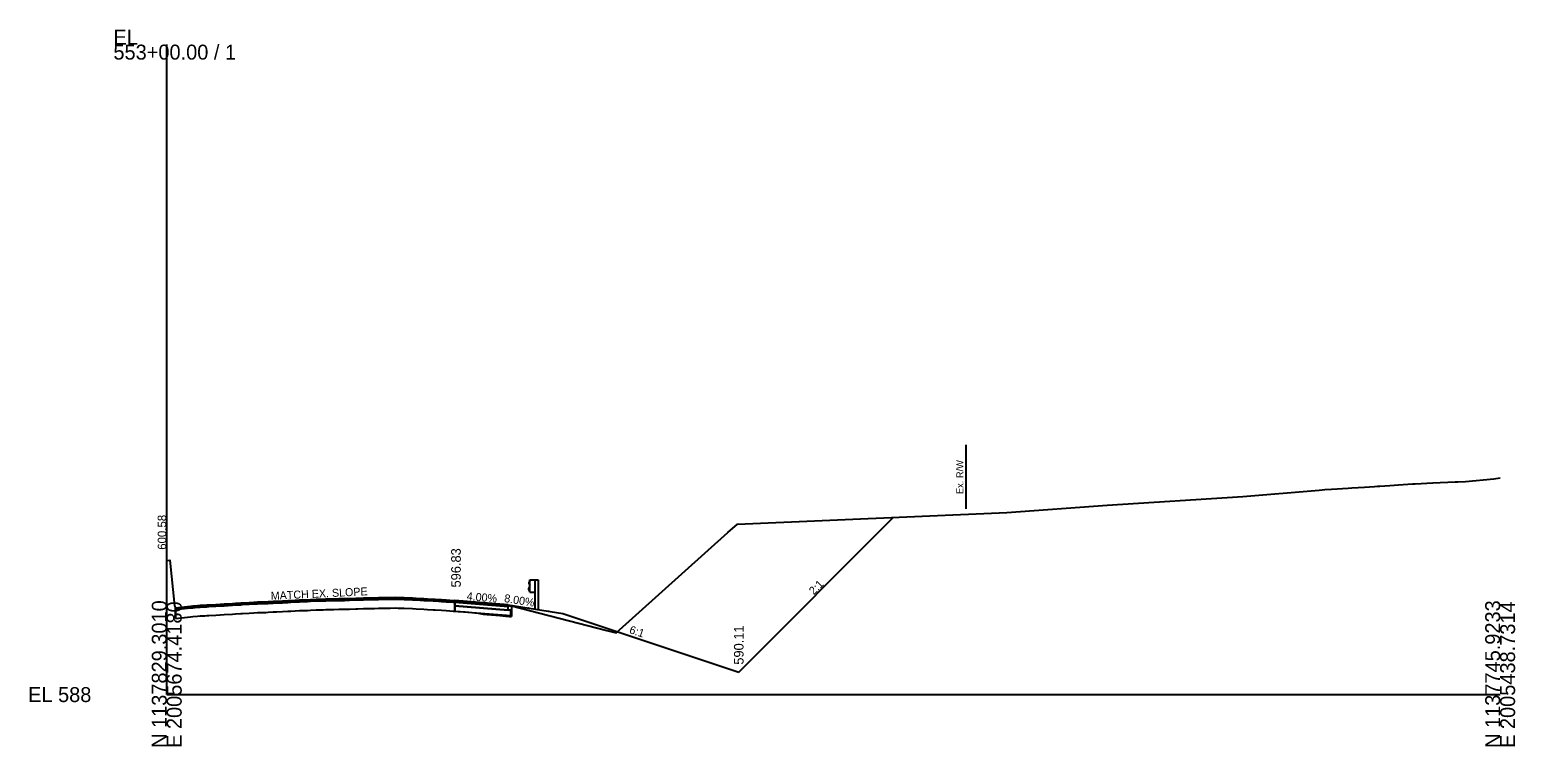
# Model space of a CAD drawing. Extents: x -201 to 2007062, y -213 to 1139737.
# Drawn here: x -25.7 to 252.8, y 7490.3 to 7624.7 of the extents above; entities that cross this region are included whole.
import ezdxf

# ---------------------------------------------------------------- set-up
doc = ezdxf.new("R2010")
doc.units = 0
for name, color, linetype in [('Default', 7, 'Continuous'), ('RD_GPK_XS_Cell', 7, 'Continuous'), ('RD_Sketch1', 7, 'Continuous'), ('RD_XS_Base', 7, 'Continuous'), ('RD_XS_EarthShd', 7, 'Continuous'), ('RD_XS_ExGround', 7, 'Continuous'), ('RD_XS_ExPaveRet', 7, 'Continuous'), ('RD_XS_ExRW', 7, 'Continuous'), ('RD_XS_GR', 7, 'Continuous'), ('RD_XS_PaveOvlay', 7, 'Continuous'), ('RD_XS_PaveShd', 7, 'Continuous'), ('RD_XS_TieSlope', 7, 'Continuous'), ('RD_XS_TX_Ditch', 7, 'Continuous'), ('RD_XS_TX_Elev_EX', 7, 'Continuous'), ('RD_XS_TX_Elev_PR', 7, 'Continuous'), ('RD_XS_TX_Slope', 7, 'Continuous')]:
    doc.layers.add(name, color=color, linetype=linetype)

msp = doc.modelspace()

# ---------------------------------------------------------------- linework, layer by layer
at = {"layer": 'RD_GPK_XS_Cell'}
for q in [(0, 7621.9), (250, 7500)]:
    msp.add_line((0, 7500), q, dxfattribs=at)
at = {"layer": 'RD_XS_Base'}
for points in [[(64, 7516.52), (54, 7517.32)], [(54, 7517.32), (54, 7516.66)], [(64.5, 7515.82), (64, 7515.86), (54, 7516.66)], [(54, 7516.66), (54, 7515.66)], [(54, 7516.66), (64, 7515.86)], [(54, 7515.66), (64.5, 7514.82)], [(64, 7515.86), (64, 7516.52)], [(64.5, 7514.82), (64.5, 7515.82)]]:
    msp.add_lwpolyline(points, dxfattribs=at)
at = {"layer": 'RD_XS_EarthShd'}
msp.add_lwpolyline([(64, 7516.85), (74.25, 7515.21)], dxfattribs=at)
at = {"layer": 'RD_XS_ExGround'}
msp.add_lwpolyline([(0, 7525.17), (0.58, 7525.19), (1.48, 7516.66), (1.64, 7516.27), (4.45, 7516.58), (4.92, 7516.63), (5.75, 7516.72), (6.29, 7516.75), (7.12, 7516.8), (7.52, 7516.82), (7.87, 7516.83), (9.18, 7516.91), (9.99, 7516.97), (10.75, 7517.02), (12.32, 7517.11), (12.9, 7517.14), (13.88, 7517.2), (14.23, 7517.22), (15.45, 7517.29), (16.35, 7517.34), (17.02, 7517.38), (18.55, 7517.43), (19.01, 7517.45), (19.97, 7517.52), (20.6, 7517.54), (21.72, 7517.57), (22.72, 7517.63), (23.29, 7517.66), (24.89, 7517.76), (26.42, 7517.8), (26.96, 7517.84), (27.99, 7517.89), (29.35, 7517.92), (29.83, 7517.94), (30.75, 7517.97), (31.34, 7517.97), (32.27, 7518), (32.69, 7518), (33.33, 7518.02), (34.26, 7518.04), (35.45, 7518.09), (35.82, 7518.1), (36.88, 7518.13), (37.57, 7518.15), (38.96, 7518.17), (39.69, 7518.2), (40.52, 7518.22), (41.89, 7518.24), (42.9, 7518.25), (43.4, 7518.24), (43.93, 7518.22), (44.51, 7518.2), (46.05, 7518.13), (46.79, 7518.09), (48.18, 7518.01), (48.88, 7517.97), (49.93, 7517.92), (50.3, 7517.9), (51.49, 7517.81), (52.42, 7517.75), (53.06, 7517.71), (53.69, 7517.67), (54.64, 7517.61), (55.03, 7517.6), (55.92, 7517.51), (56.66, 7517.44), (57.76, 7517.34), (58.37, 7517.3), (59, 7517.15), (59.31, 7517.11), (60, 7517.01), (60.91, 7516.94), (62.46, 7516.83), (63.03, 7516.77), (63.6, 7516.7), (64.25, 7516.64), (64.66, 7516.63), (82.53, 7512.02), (84.29, 7511.58), (105.23, 7530.38), (107, 7531.96), (157.52, 7534.18), (176.33, 7535.52), (201.74, 7537.17), (216.08, 7538.37), (216.61, 7538.4), (217.12, 7538.44), (218.37, 7538.52), (221.52, 7538.73), (222.18, 7538.77), (224.59, 7538.93), (226.42, 7539.05), (227, 7539.08), (227.42, 7539.11), (229.32, 7539.24), (230.93, 7539.34), (233.56, 7539.51), (234.07, 7539.54), (237.38, 7539.7), (241.58, 7539.9), (242.05, 7539.92), (243.52, 7540), (248.82, 7540.5), (250, 7540.63)], dxfattribs=at)
at = {"layer": 'RD_XS_ExPaveRet'}
for p, q in [((1.64, 7514.27), (1.64, 7516.27)), ((1.64, 7515.94), (1.64, 7514.27)), ((7.12, 7514.8), (7.52, 7514.82)), ((7.12, 7514.8), (7.52, 7514.82)), ((7.52, 7514.82), (7.87, 7514.83)), ((7.52, 7514.82), (7.87, 7514.83)), ((7.87, 7514.83), (9.18, 7514.91)), ((7.87, 7514.83), (9.18, 7514.91)), ((9.18, 7514.91), (9.99, 7514.97)), ((9.18, 7514.91), (9.99, 7514.97)), ((9.99, 7514.97), (10.75, 7515.02)), ((9.99, 7514.97), (10.75, 7515.02)), ((10.75, 7515.02), (12.32, 7515.11)), ((10.75, 7515.02), (12.32, 7515.11)), ((12.32, 7515.11), (12.9, 7515.14)), ((12.32, 7515.11), (12.9, 7515.14)), ((12.9, 7515.14), (13.88, 7515.2)), ((12.9, 7515.14), (13.88, 7515.2)), ((13.88, 7515.2), (14.23, 7515.22)), ((13.88, 7515.2), (14.23, 7515.22)), ((14.23, 7515.22), (15.45, 7515.29)), ((14.23, 7515.22), (15.45, 7515.29)), ((15.45, 7515.29), (16.35, 7515.34)), ((15.45, 7515.29), (16.35, 7515.34)), ((16.35, 7515.34), (17.02, 7515.38)), ((16.35, 7515.34), (17.02, 7515.38)), ((17.02, 7515.38), (18.55, 7515.43)), ((17.02, 7515.38), (18.55, 7515.43)), ((18.55, 7515.43), (19.01, 7515.45)), ((18.55, 7515.43), (19.01, 7515.45)), ((19.01, 7515.45), (19.97, 7515.52)), ((19.01, 7515.45), (19.97, 7515.52)), ((19.97, 7515.52), (20.6, 7515.54)), ((19.97, 7515.52), (20.6, 7515.54)), ((20.6, 7515.54), (21.72, 7515.57)), ((20.6, 7515.54), (21.72, 7515.57)), ((21.72, 7515.57), (22.72, 7515.63)), ((21.72, 7515.57), (22.72, 7515.63)), ((22.72, 7515.63), (23.29, 7515.66)), ((22.72, 7515.63), (23.29, 7515.66)), ((23.29, 7515.66), (24.89, 7515.76)), ((23.29, 7515.66), (24.89, 7515.76)), ((24.89, 7515.76), (26.42, 7515.8)), ((24.89, 7515.76), (26.42, 7515.8)), ((26.42, 7515.8), (26.96, 7515.84)), ((26.42, 7515.8), (26.96, 7515.84)), ((26.96, 7515.84), (27.99, 7515.89)), ((26.96, 7515.84), (27.99, 7515.89)), ((27.99, 7515.89), (29.35, 7515.92)), ((27.99, 7515.89), (29.35, 7515.92)), ((29.35, 7515.92), (29.83, 7515.94)), ((29.35, 7515.92), (29.83, 7515.94)), ((29.83, 7515.94), (30.75, 7515.97)), ((29.83, 7515.94), (30.75, 7515.97)), ((30.75, 7515.97), (31.34, 7515.97)), ((30.75, 7515.97), (31.34, 7515.97)), ((31.34, 7515.97), (32.27, 7516)), ((31.34, 7515.97), (32.27, 7516)), ((32.27, 7516), (32.69, 7516)), ((32.27, 7516), (32.69, 7516)), ((32.69, 7516), (33.33, 7516.02)), ((32.69, 7516), (33.33, 7516.02)), ((33.33, 7516.02), (34.26, 7516.04)), ((33.33, 7516.02), (34.26, 7516.04)), ((34.26, 7516.04), (35.45, 7516.09)), ((34.26, 7516.04), (35.45, 7516.09)), ((35.45, 7516.09), (35.82, 7516.1)), ((35.45, 7516.09), (35.82, 7516.1)), ((35.82, 7516.1), (36.88, 7516.13)), ((35.82, 7516.1), (36.88, 7516.13)), ((36.88, 7516.13), (37.57, 7516.15)), ((36.88, 7516.13), (37.57, 7516.15)), ((37.57, 7516.15), (38.96, 7516.17)), ((37.57, 7516.15), (38.96, 7516.17)), ((38.96, 7516.17), (39.69, 7516.2)), ((38.96, 7516.17), (39.69, 7516.2)), ((39.69, 7516.2), (40.52, 7516.22)), ((39.69, 7516.2), (40.52, 7516.22)), ((40.52, 7516.22), (41.89, 7516.24)), ((40.52, 7516.22), (41.89, 7516.24)), ((41.89, 7516.24), (42.9, 7516.25)), ((41.89, 7516.24), (42.9, 7516.25)), ((42.9, 7516.25), (43.4, 7516.24)), ((42.9, 7516.25), (43.4, 7516.24)), ((43.4, 7516.24), (43.93, 7516.22)), ((43.4, 7516.24), (43.93, 7516.22)), ((43.93, 7516.22), (44.51, 7516.2)), ((43.93, 7516.22), (44.51, 7516.2)), ((44.51, 7516.2), (46.05, 7516.13)), ((44.51, 7516.2), (46.05, 7516.13)), ((46.05, 7516.13), (46.79, 7516.09)), ((46.05, 7516.13), (46.79, 7516.09)), ((46.79, 7516.09), (48.18, 7516.01)), ((46.79, 7516.09), (48.18, 7516.01)), ((48.18, 7516.01), (48.88, 7515.97)), ((48.18, 7516.01), (48.88, 7515.97)), ((48.88, 7515.97), (49.93, 7515.92)), ((48.88, 7515.97), (49.93, 7515.92)), ((49.93, 7515.92), (50.3, 7515.9)), ((49.93, 7515.92), (50.3, 7515.9)), ((50.3, 7515.9), (51.49, 7515.81)), ((50.3, 7515.9), (51.49, 7515.81)), ((51.49, 7515.81), (52.42, 7515.75)), ((51.49, 7515.81), (52.42, 7515.75)), ((52.42, 7515.75), (53.06, 7515.71)), ((52.42, 7515.75), (53.06, 7515.71)), ((53.06, 7515.71), (53.69, 7515.67)), ((53.06, 7515.71), (53.69, 7515.67)), ((53.69, 7515.67), (54.64, 7515.61)), ((53.69, 7515.67), (54, 7515.65)), ((54, 7516.66), (54, 7517.32)), ((54, 7517.32), (54, 7517.32)), ((54, 7515.66), (54, 7516.66)), ((54, 7515.66), (54, 7515.65)), ((54, 7515.65), (54, 7515.66)), ((54.64, 7515.61), (55.03, 7515.6)), ((55.03, 7515.6), (55.92, 7515.51)), ((55.92, 7515.51), (56.66, 7515.44)), ((56.66, 7515.44), (57.76, 7515.34)), ((57.76, 7515.34), (58.37, 7515.3)), ((58.37, 7515.3), (59, 7515.15)), ((59, 7515.15), (59.31, 7515.11)), ((59.31, 7515.11), (60, 7515.01)), ((60, 7515.01), (60.91, 7514.94)), ((60.91, 7514.94), (62.46, 7514.83)), ((62.46, 7514.83), (63.03, 7514.77)), ((64.66, 7516.63), (64.66, 7514.63)), ((1.64, 7514.27), (4.45, 7514.58)), ((1.64, 7514.27), (4.45, 7514.58)), ((1.64, 7514.27), (1.64, 7514.27)), ((1.64, 7514.27), (1.64, 7514.27)), ((4.45, 7514.58), (4.92, 7514.63)), ((4.45, 7514.58), (4.92, 7514.63)), ((4.92, 7514.63), (5.75, 7514.72)), ((4.92, 7514.63), (5.75, 7514.72)), ((5.75, 7514.72), (6.29, 7514.75)), ((5.75, 7514.72), (6.29, 7514.75)), ((6.29, 7514.75), (7.12, 7514.8)), ((6.29, 7514.75), (7.12, 7514.8)), ((63.03, 7514.77), (63.6, 7514.7)), ((63.6, 7514.7), (64.25, 7514.64)), ((64.25, 7514.64), (64.66, 7514.63))]:
    msp.add_line(p, q, dxfattribs=at)
for points in [[(54, 7517.32), (53.69, 7517.33), (53.06, 7517.38), (52.42, 7517.42), (51.49, 7517.48), (50.3, 7517.56), (49.93, 7517.58), (48.88, 7517.64), (48.18, 7517.68), (46.79, 7517.75), (46.05, 7517.79), (44.51, 7517.86), (43.93, 7517.89), (43.4, 7517.9), (42.9, 7517.92), (41.89, 7517.91), (40.52, 7517.89), (39.69, 7517.87), (38.96, 7517.84), (37.57, 7517.82), (36.88, 7517.8), (35.82, 7517.77), (35.45, 7517.76), (34.26, 7517.71), (33.33, 7517.68), (32.69, 7517.67), (32.27, 7517.67), (31.34, 7517.64), (30.75, 7517.64), (29.83, 7517.6), (29.35, 7517.59), (27.99, 7517.56), (26.96, 7517.51), (26.42, 7517.47), (24.89, 7517.43), (23.29, 7517.32), (22.72, 7517.29), (21.72, 7517.24), (20.6, 7517.21), (19.97, 7517.18), (19.01, 7517.12), (18.55, 7517.1), (17.02, 7517.04), (16.35, 7517.01), (15.45, 7516.96), (14.23, 7516.89), (13.88, 7516.86), (12.9, 7516.81), (12.32, 7516.78), (10.75, 7516.68), (9.99, 7516.64), (9.18, 7516.58), (7.87, 7516.5), (7.52, 7516.48), (7.12, 7516.47), (6.29, 7516.42), (5.75, 7516.39), (4.92, 7516.3), (4.45, 7516.25), (1.64, 7515.94)], [(1.64, 7515.94), (1.64, 7515.94)]]:
    msp.add_lwpolyline(points, dxfattribs=at)
at = {"layer": 'RD_XS_ExRW'}
msp.add_line((149.85, 7546.85), (149.85, 7534.85), dxfattribs=at)
at = {"layer": 'RD_XS_GR'}
for p, q in [((68.07, 7521.39), (67.91, 7520.99)), ((67.91, 7520.99), (67.91, 7520.89)), ((67.91, 7520.89), (68.07, 7520.49)), ((68.07, 7519.21), (68.07, 7521.54)), ((68.07, 7521.54), (68.99, 7521.54)), ((68.99, 7521.54), (68.99, 7516.04)), ((68.99, 7521.54), (69.66, 7521.54)), ((69.66, 7521.54), (69.66, 7515.93)), ((67.91, 7519.85), (68.07, 7520.25)), ((67.91, 7519.75), (67.91, 7519.85)), ((68.07, 7519.35), (67.91, 7519.75)), ((68.07, 7519.21), (68.99, 7519.21))]:
    msp.add_line(p, q, dxfattribs=at)
for centre, major_axis in [((67.91, 7516.23), (0, -0.02)), ((71.66, 7515.63), (0, -0.0204))]:
    msp.add_ellipse(centre, major_axis=major_axis, ratio=0.5, dxfattribs=at)
at = {"layer": 'RD_XS_PaveOvlay'}
for points in [[(1.64, 7516.27), (1.64, 7516.27), (4.45, 7516.58), (4.92, 7516.63), (5.75, 7516.72), (6.29, 7516.75), (7.12, 7516.8), (7.52, 7516.82), (7.87, 7516.83), (9.18, 7516.91), (9.99, 7516.97), (10.75, 7517.02), (12.32, 7517.11), (12.9, 7517.14), (13.88, 7517.2), (14.23, 7517.22), (15.45, 7517.29), (16.35, 7517.34), (17.02, 7517.38), (18.55, 7517.43), (19.01, 7517.45), (19.97, 7517.52), (20.6, 7517.54), (21.72, 7517.57), (22.72, 7517.63), (23.29, 7517.66), (24.89, 7517.76), (26.42, 7517.8), (26.96, 7517.84), (27.99, 7517.89), (29.35, 7517.92), (29.83, 7517.94), (30.75, 7517.97), (31.34, 7517.97), (32.27, 7518), (32.69, 7518), (33.33, 7518.02), (34.26, 7518.04), (35.45, 7518.09), (35.82, 7518.1), (36.88, 7518.13), (37.57, 7518.15), (38.96, 7518.17), (39.69, 7518.2), (40.52, 7518.22), (41.89, 7518.24), (42.9, 7518.25), (43.4, 7518.24), (43.93, 7518.22), (44.51, 7518.2), (46.05, 7518.13), (46.79, 7518.09), (48.18, 7518.01), (48.88, 7517.97), (49.93, 7517.92), (50.3, 7517.9), (51.49, 7517.81), (52.42, 7517.75), (53.06, 7517.71), (53.69, 7517.67), (54, 7517.65)], [(1.64, 7515.94), (1.64, 7515.94), (4.45, 7516.25), (4.92, 7516.3), (5.75, 7516.39), (6.29, 7516.42), (7.12, 7516.47), (7.52, 7516.48), (7.87, 7516.5), (9.18, 7516.58), (9.99, 7516.64), (10.75, 7516.68), (12.32, 7516.78), (12.9, 7516.81), (13.88, 7516.86), (14.23, 7516.89), (15.45, 7516.96), (16.35, 7517.01), (17.02, 7517.04), (18.55, 7517.1), (19.01, 7517.12), (19.97, 7517.18), (20.6, 7517.21), (21.72, 7517.24), (22.72, 7517.29), (23.29, 7517.32), (24.89, 7517.43), (26.42, 7517.47), (26.96, 7517.51), (27.99, 7517.56), (29.35, 7517.59), (29.83, 7517.6), (30.75, 7517.64), (31.34, 7517.64), (32.27, 7517.67), (32.69, 7517.67), (33.33, 7517.68), (34.26, 7517.71), (35.45, 7517.76), (35.82, 7517.77), (36.88, 7517.8), (37.57, 7517.82), (38.96, 7517.84), (39.69, 7517.87), (40.52, 7517.89), (41.89, 7517.91), (42.9, 7517.92), (43.4, 7517.9), (43.93, 7517.89), (44.51, 7517.86), (46.05, 7517.79), (46.79, 7517.75), (48.18, 7517.68), (48.88, 7517.64), (49.93, 7517.58), (50.3, 7517.56), (51.49, 7517.48), (52.42, 7517.42), (53.06, 7517.38), (53.69, 7517.33), (54, 7517.32)]]:
    msp.add_lwpolyline(points, dxfattribs=at)
at = {"layer": 'RD_XS_PaveShd'}
for points in [[(64, 7516.85), (54, 7517.65)], [(54, 7517.65), (54, 7517.32)], [(54, 7517.32), (64, 7516.52)], [(64, 7516.52), (64, 7516.85)]]:
    msp.add_lwpolyline(points, dxfattribs=at)
at = {"layer": 'RD_XS_TieSlope'}
msp.add_line((74.25, 7515.21), (107.25, 7504.21), dxfattribs=at)
msp.add_lwpolyline([(107.25, 7504.21), (136.28, 7533.25)], dxfattribs=at)

# ---------------------------------------------------------------- texts
at = {"layer": 'Default'}
msp.add_text('-', height=0.0001, dxfattribs=at).set_placement((0, 7500))
at = {"layer": 'RD_GPK_XS_Cell'}
for s, p in [('EL', (-10, 7621.9)), ('553+00.00 / 1', (-10, 7619.1)), ('EL 588', (-26, 7498.6))]:
    msp.add_text(s, height=2.8, dxfattribs=at).set_placement(p)
for s, p in [('N 1137829.3010', (0, 7490)), ('E 2005674.4180', (2.8, 7490)), ('N 1137745.9233', (250, 7490)), ('E 2005438.7314', (252.8, 7490))]:
    msp.add_text(s, height=2.8, rotation=90, dxfattribs=at).set_placement(p)
at = {"layer": 'RD_Sketch1'}
for s, p in [('Exterior Boundary', (127.47, 7532.83)), ('LOC_C', (127.8, 7532.83)), ('Exterior Boundary', (53.44, 7517.6)), ('EP_X_R', (53.73, 7517.6)), ('EP_X2', (53.79, 7516.61)), ('EP_X3', (53.79, 7515.61)), ('EP_X1', (53.8, 7517.27)), ('ESP1_R', (63.73, 7516.47)), ('ESP2_R', (63.73, 7515.81)), ('ESP_R', (63.77, 7516.8)), ('ESP4_R', (64.23, 7515.77)), ('ESP3_R', (64.23, 7514.77)), ('ES_R', (65.82, 7516.48))]:
    msp.add_text(s, height=0.05, dxfattribs=at).set_placement(p)
at = {"layer": 'RD_XS_ExRW'}
msp.add_text('Ex. R/W ', height=1.3, rotation=90, dxfattribs=at).set_placement((149.35, 7537.61))
at = {"layer": 'RD_XS_TX_Ditch'}
msp.add_text('590.11', height=1.8, rotation=90, dxfattribs=at).set_placement((108.15, 7505.61))
at = {"layer": 'RD_XS_TX_Elev_EX'}
msp.add_text('600.58', height=1.6, rotation=90, dxfattribs=at).set_placement((-0.1, 7527.17))
at = {"layer": 'RD_XS_TX_Elev_PR'}
msp.add_text('596.83', height=1.8, rotation=90, dxfattribs=at).set_placement((55.13, 7520.09))
at = {"layer": 'RD_XS_TX_Slope'}
for s, rotation, p in [('2:1', 45, (121.31, 7518.63)), ('MATCH EX. SLOPE', 2.7318, (19.54, 7517.77)), ('4.00%', 355.4261, (56.2, 7517.73)), ('8.00%', 350.9097, (63.2, 7517.38)), ('6:1', 341.5651, (86.61, 7511.56))]:
    msp.add_text(s, height=1.5, rotation=rotation, dxfattribs=at).set_placement(p)

doc.saveas('drawing.dxf')
